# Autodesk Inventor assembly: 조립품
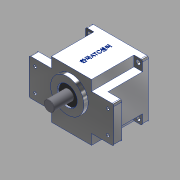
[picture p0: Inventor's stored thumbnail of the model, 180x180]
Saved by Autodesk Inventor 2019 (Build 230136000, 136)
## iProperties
Created: 2020-01
Part Number: 조립품
Material: 일반
Document SubType Name: Assembly
Designer: 323-10
Author: 323-10
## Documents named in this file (10)
- C:\Users\323-10\Desktop\700119V1003\조립품.iam
- C:\Users\323-10\Desktop\700119V1003\본체.ipt
- C:\Users\323-10\Desktop\700119V1003\커버.ipt
- C:\Users\323-10\Desktop\700119V1003\메인 축.ipt
- C:\Users\323-10\Desktop\700119V1003\서브 축.ipt
- C:\Users\323-10\Desktop\700119V1003\볼트 M4.ipt
- C:\Users\323-10\Desktop\700119V1003\베어링 6003.ipt
- C:\Users\323-10\Desktop\700119V1003\베어링 608.ipt
- C:\Users\323-10\Desktop\700119V1003\오일 실 17 32 8.ipt
- C:\Users\323-10\Desktop\700119V1003\오일 실 8 22 7.ipt
